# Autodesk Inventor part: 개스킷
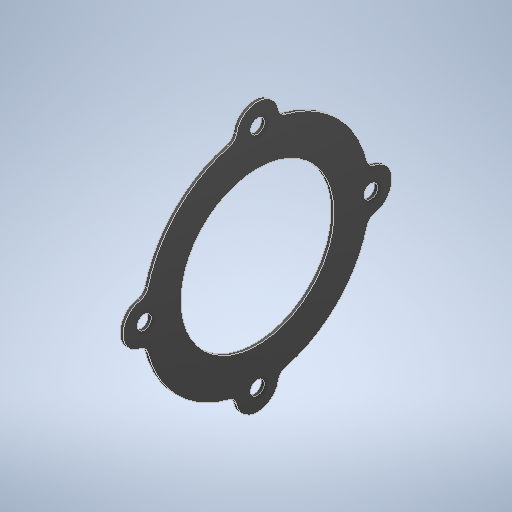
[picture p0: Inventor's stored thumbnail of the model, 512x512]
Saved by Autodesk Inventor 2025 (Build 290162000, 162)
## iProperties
Created: 2024-08
Part Number: 개스킷
Material: 황동, 연질 노란색
Document SubType Name: Modeling
Designer: onair
Density: 8.47 g/cm^3
Appearance: 기본값
Author: jhkim
Sending System: Autodesk Inventor 2025
Preprocessor: ST-DEVELOPER v20
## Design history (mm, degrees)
feature "솔리드2"
node "솔리드1"
